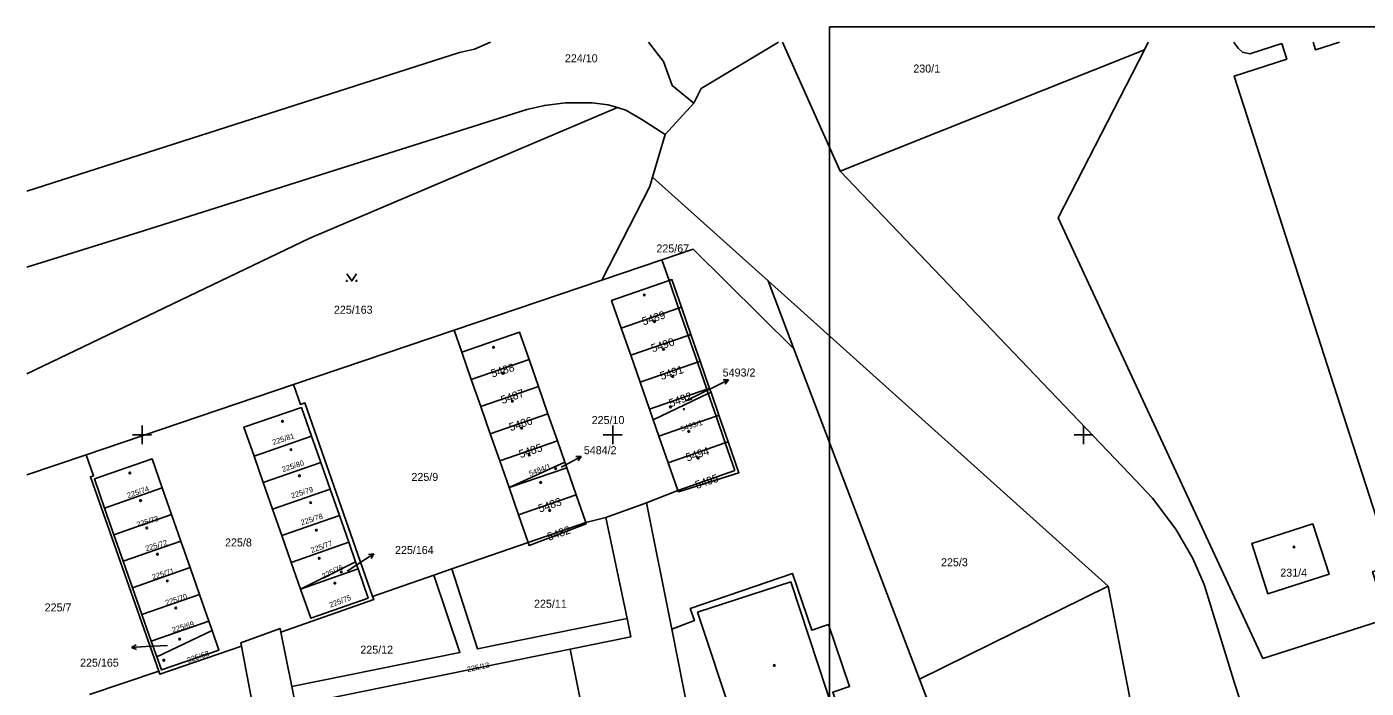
# Model space of a CAD drawing. Extents: x -599970 to -599524, y -1154772 to -1154457.
# Drawn here: x -599962.2 to -599820, y -1154526.9 to -1154456.7 of the extents above; entities that cross this region are included whole.
import ezdxf

# ---------------------------------------------------------------- set-up
doc = ezdxf.new("R2010")
doc.units = 0
for name, color, linetype in [('Z-KATASTRALNI MAPA', 7, 'Continuous'), ('Z-KRIZKY CTVERCOVE SITE', 7, 'Continuous'), ('Z-RAM ROZPISKA', 7, 'Continuous')]:
    doc.layers.add(name, color=color, linetype=linetype)

msp = doc.modelspace()

# ---------------------------------------------------------------- linework, layer by layer
at = {"layer": 'Z-KATASTRALNI MAPA'}
for p, q in [((-599875.84, -1154471.97), (-599881.95, -1154458.29)), ((-599875.84, -1154471.97), (-599843.53, -1154459.09)), ((-599891.38, -1154464.75), (-599894.44, -1154468.08)), ((-599895.76, -1154472.61), (-599894.44, -1154468.08)), ((-599895.76, -1154472.61), (-599883.5, -1154483.62)), ((-599894.78, -1154481.41), (-599901.15, -1154483.56)), ((-599894.02, -1154483.6), (-599894.78, -1154481.41)), ((-599916.86, -1154488.87), (-599901.15, -1154483.56)), ((-599894.02, -1154483.6), (-599893, -1154486.54)), ((-599883.5, -1154483.62), (-599880.75, -1154490.86)), ((-599883.5, -1154483.62), (-599847.36, -1154516.07)), ((-599893, -1154486.54), (-599892, -1154489.43)), ((-599892.7, -1154486.44), (-599891.7, -1154489.33)), ((-599933.91, -1154494.65), (-599916.86, -1154488.87)), ((-599916.04, -1154491.21), (-599916.86, -1154488.87)), ((-599898.09, -1154491.54), (-599899.1, -1154488.65)), ((-599892, -1154489.43), (-599891.01, -1154492.27)), ((-599891.7, -1154489.33), (-599890.71, -1154492.17)), ((-599915.03, -1154494.1), (-599916.04, -1154491.21)), ((-599897.1, -1154494.39), (-599898.09, -1154491.54)), ((-599880.75, -1154490.86), (-599867.42, -1154525.94)), ((-599908.89, -1154491.98), (-599915.03, -1154494.1)), ((-599908.89, -1154491.98), (-599907.88, -1154494.87)), ((-599891.01, -1154492.27), (-599890.01, -1154495.16)), ((-599890.71, -1154492.17), (-599889.71, -1154495.06)), ((-599955.94, -1154502.11), (-599933.91, -1154494.65)), ((-599914.02, -1154496.98), (-599915.03, -1154494.1)), ((-599896.09, -1154497.28), (-599897.1, -1154494.39)), ((-599889.06, -1154494.82), (-599887.71, -1154494.16)), ((-599887.71, -1154494.16), (-599888.27, -1154494.16)), ((-599887.71, -1154494.16), (-599888.05, -1154494.61)), ((-599907.88, -1154494.87), (-599914.02, -1154496.98)), ((-599907.88, -1154494.87), (-599906.88, -1154497.76)), ((-599892.22, -1154496.37), (-599889.06, -1154494.82)), ((-599890.01, -1154495.16), (-599889.85, -1154495.62)), ((-599889.85, -1154495.62), (-599889.02, -1154498.01)), ((-599889.71, -1154495.06), (-599889.56, -1154495.49)), ((-599889.56, -1154495.49), (-599888.72, -1154497.91)), ((-599913.01, -1154499.87), (-599914.02, -1154496.98)), ((-599895.7, -1154498.41), (-599896.09, -1154497.28)), ((-599906.88, -1154497.76), (-599913.01, -1154499.87)), ((-599906.88, -1154497.76), (-599905.87, -1154500.64)), ((-599895.1, -1154500.13), (-599895.7, -1154498.41)), ((-599889.02, -1154498.01), (-599888.04, -1154500.85)), ((-599888.72, -1154497.91), (-599887.74, -1154500.74)), ((-599931.98, -1154500.12), (-599938.1, -1154502.26)), ((-599931.98, -1154500.12), (-599931, -1154502.93)), ((-599912.01, -1154502.76), (-599913.01, -1154499.87)), ((-599894.11, -1154502.97), (-599895.1, -1154500.13)), ((-599912.01, -1154502.76), (-599905.87, -1154500.64)), ((-599905.87, -1154500.64), (-599905.1, -1154502.88)), ((-599887.02, -1154503.79), (-599888.04, -1154500.85)), ((-599955.94, -1154502.11), (-599962.24, -1154504.25)), ((-599937.12, -1154505.07), (-599938.1, -1154502.26)), ((-599931, -1154502.93), (-599937.12, -1154505.07)), ((-599931, -1154502.93), (-599930.02, -1154505.75)), ((-599911.01, -1154505.6), (-599912.01, -1154502.76)), ((-599911.01, -1154505.6), (-599905.1, -1154502.88)), ((-599905.49, -1154503.43), (-599904.68, -1154502.99)), ((-599905.1, -1154502.88), (-599904.89, -1154503.49)), ((-599904.68, -1154502.99), (-599903.35, -1154502.29)), ((-599903.35, -1154502.29), (-599903.92, -1154502.3)), ((-599903.35, -1154502.29), (-599903.68, -1154502.74)), ((-599893.09, -1154505.91), (-599894.11, -1154502.97)), ((-599904.89, -1154503.49), (-599911.01, -1154505.6)), ((-599904.89, -1154503.49), (-599903.88, -1154506.37)), ((-599893.09, -1154505.91), (-599887.02, -1154503.79)), ((-599947.86, -1154505.64), (-599953.98, -1154507.78)), ((-599947.86, -1154505.64), (-599946.87, -1154508.47)), ((-599936.13, -1154507.89), (-599937.12, -1154505.07)), ((-599930.02, -1154505.75), (-599936.13, -1154507.89)), ((-599930.02, -1154505.75), (-599929.03, -1154508.57)), ((-599910.01, -1154508.49), (-599911.01, -1154505.6)), ((-599896.4, -1154507.21), (-599893.09, -1154505.91)), ((-599903.88, -1154506.37), (-599910.01, -1154508.49)), ((-599903.88, -1154506.37), (-599902.86, -1154509.31)), ((-599900.72, -1154508.78), (-599896.4, -1154507.21)), ((-599893.73, -1154520.65), (-599896.4, -1154507.21)), ((-599952.99, -1154510.61), (-599953.98, -1154507.78)), ((-599946.87, -1154508.47), (-599952.99, -1154510.61)), ((-599946.87, -1154508.47), (-599945.88, -1154511.28)), ((-599935.14, -1154510.7), (-599936.13, -1154507.89)), ((-599929.03, -1154508.57), (-599935.14, -1154510.7)), ((-599929.03, -1154508.57), (-599928.04, -1154511.41)), ((-599908.98, -1154511.42), (-599910.01, -1154508.49)), ((-599902.86, -1154509.31), (-599900.72, -1154508.78)), ((-599898.48, -1154519.5), (-599900.72, -1154508.78)), ((-599908.98, -1154511.42), (-599902.86, -1154509.31)), ((-599952.01, -1154513.42), (-599952.99, -1154510.61)), ((-599945.88, -1154511.28), (-599952.01, -1154513.42)), ((-599945.88, -1154511.28), (-599944.9, -1154514.1)), ((-599934.15, -1154513.55), (-599935.14, -1154510.7)), ((-599928.04, -1154511.41), (-599934.15, -1154513.55)), ((-599928.04, -1154511.41), (-599927.32, -1154513.47)), ((-599917.1, -1154514.24), (-599908.98, -1154511.42)), ((-599926.64, -1154513.45), (-599925.38, -1154512.63)), ((-599925.38, -1154512.63), (-599925.94, -1154512.7)), ((-599925.38, -1154512.63), (-599925.67, -1154513.12)), ((-599951.02, -1154516.24), (-599952.01, -1154513.42)), ((-599944.9, -1154514.1), (-599951.02, -1154516.24)), ((-599944.9, -1154514.1), (-599943.9, -1154516.95)), ((-599933.16, -1154516.38), (-599934.15, -1154513.55)), ((-599933.16, -1154516.38), (-599927.32, -1154513.47)), ((-599927.05, -1154514.24), (-599933.16, -1154516.38)), ((-599928.21, -1154514.48), (-599926.64, -1154513.45)), ((-599927.32, -1154513.47), (-599927.05, -1154514.24)), ((-599918.99, -1154514.91), (-599917.1, -1154514.24)), ((-599925.51, -1154517.16), (-599918.99, -1154514.91)), ((-599891, -1154518.82), (-599881.1, -1154515.6)), ((-599881.1, -1154515.6), (-599875.33, -1154533.01)), ((-599867.42, -1154525.94), (-599847.36, -1154516.07)), ((-599847.36, -1154516.07), (-599840.68, -1154550.58)), ((-599950.03, -1154519.09), (-599951.02, -1154516.24)), ((-599943.9, -1154516.95), (-599950.03, -1154519.09)), ((-599943.9, -1154516.95), (-599942.91, -1154519.78)), ((-599891, -1154518.82), (-599885.15, -1154536.36)), ((-599949.04, -1154521.92), (-599950.03, -1154519.09)), ((-599949.04, -1154521.92), (-599942.91, -1154519.78)), ((-599942.91, -1154519.78), (-599942.56, -1154520.77)), ((-599942.56, -1154520.77), (-599948.43, -1154523.58)), ((-599935.24, -1154520.95), (-599934.08, -1154526.74)), ((-599890.22, -1154538.37), (-599893.73, -1154520.65)), ((-599951.11, -1154522.57), (-599950.62, -1154522.29)), ((-599949.61, -1154522.49), (-599951.11, -1154522.57)), ((-599951.11, -1154522.57), (-599950.6, -1154522.79)), ((-599947.29, -1154522.38), (-599949.61, -1154522.49)), ((-599948.43, -1154523.58), (-599949.04, -1154521.92)), ((-599939.42, -1154522.44), (-599937.69, -1154531.73)), ((-599933.69, -1154528.7), (-599904.52, -1154522.77)), ((-599955.57, -1154527.59), (-599948.23, -1154525.08)), ((-599934.08, -1154526.74), (-599933.69, -1154528.7))]:
    msp.add_line(p, q, dxfattribs=at)
for points in [[(-599962.24, -1154474.12), (-599916.27, -1154459.39), (-599914.68, -1154459.01), (-599912.98, -1154458.29)], [(-599896.19, -1154458.29), (-599894.62, -1154460.32), (-599893.67, -1154462.88), (-599891.38, -1154464.75)], [(-599882.41, -1154458.29), (-599890.62, -1154463.2), (-599891.38, -1154464.75)], [(-599843.53, -1154459.09), (-599852.7, -1154476.94), (-599830.94, -1154523.74), (-599794.88, -1154512.22)], [(-599843.12, -1154458.29), (-599843.53, -1154459.09)], [(-599834.01, -1154458.29), (-599834, -1154458.35), (-599833.58, -1154458.92), (-599833.1, -1154459.33), (-599832.33, -1154459.52), (-599828.94, -1154458.42)], [(-599828.94, -1154458.42), (-599828.4, -1154460.08), (-599833.99, -1154461.88), (-599817.26, -1154513.88), (-599819.29, -1154514.53), (-599818.39, -1154517.37), (-599802.13, -1154512.18), (-599807.35, -1154495.82), (-599805.22, -1154495.14)], [(-599822.81, -1154458.29), (-599825.34, -1154459.1), (-599825.61, -1154458.29)], [(-599899.51, -1154465.24), (-599900.48, -1154464.94), (-599902.2, -1154464.73), (-599905, -1154464.73), (-599907.25, -1154465.01), (-599909.11, -1154465.44), (-599949.83, -1154478.34), (-599962.24, -1154482.17)], [(-599962.24, -1154493.52), (-599932.19, -1154479.12), (-599899.51, -1154465.24)], [(-599894.44, -1154468.08), (-599896.91, -1154466.5), (-599898.62, -1154465.52), (-599899.51, -1154465.24)], [(-599820, -1154569.28), (-599833.91, -1154526.47), (-599837.18, -1154515.88), (-599838.39, -1154513.13), (-599840.19, -1154510.02), (-599842.65, -1154506.72), (-599845.1, -1154504.12), (-599875.84, -1154471.97)], [(-599901.15, -1154483.56), (-599896.05, -1154473.6), (-599895.76, -1154472.61)], [(-599880.75, -1154490.86), (-599891.46, -1154480.28), (-599894.78, -1154481.41)], [(-599928.23, -1154482.9), (-599927.73, -1154483.65), (-599927.23, -1154482.9)], [(-599899.1, -1154488.65), (-599900.12, -1154485.71), (-599894.02, -1154483.6)], [(-599894.02, -1154483.6), (-599893.72, -1154483.5), (-599892.7, -1154486.44)], [(-599899.1, -1154488.65), (-599893, -1154486.54), (-599892.7, -1154486.44)], [(-599916.04, -1154491.21), (-599909.89, -1154489.09), (-599908.89, -1154491.98)], [(-599898.09, -1154491.54), (-599892, -1154489.43), (-599891.7, -1154489.33)], [(-599897.1, -1154494.39), (-599891.01, -1154492.27), (-599890.71, -1154492.17)], [(-599925.51, -1154517.16), (-599932.7, -1154496.6), (-599933.17, -1154496.77), (-599933.91, -1154494.65)], [(-599896.09, -1154497.28), (-599890.01, -1154495.16), (-599889.71, -1154495.06)], [(-599889.56, -1154495.49), (-599889.85, -1154495.62), (-599895.7, -1154498.41)], [(-599938.1, -1154502.26), (-599939.17, -1154499.19), (-599933.06, -1154497.09), (-599931.98, -1154500.12)], [(-599888.72, -1154497.91), (-599889.02, -1154498.01), (-599895.1, -1154500.13)], [(-599894.11, -1154502.97), (-599888.04, -1154500.85), (-599887.74, -1154500.74)], [(-599887.74, -1154500.74), (-599886.6, -1154504.02), (-599893.03, -1154506.04), (-599893.09, -1154505.91)], [(-599948.23, -1154525.08), (-599955.49, -1154504.45), (-599955.15, -1154504.35), (-599955.94, -1154502.11)], [(-599953.98, -1154507.78), (-599955.04, -1154504.67), (-599948.93, -1154502.56), (-599947.86, -1154505.64)], [(-599902.86, -1154509.31), (-599902.83, -1154509.44), (-599908.87, -1154511.75), (-599908.98, -1154511.42)], [(-599825.64, -1154509.44), (-599823.91, -1154514.8), (-599830.4, -1154516.89), (-599832.13, -1154511.52), (-599825.64, -1154509.44)], [(-599927.05, -1154514.24), (-599925.98, -1154517.33), (-599932.08, -1154519.47), (-599933.16, -1154516.38)], [(-599917.1, -1154514.24), (-599914.38, -1154522.73), (-599898.48, -1154519.5)], [(-599934.08, -1154526.74), (-599916.24, -1154523.11), (-599918.99, -1154514.91)], [(-599893.73, -1154520.65), (-599891.32, -1154519.73), (-599891.77, -1154518.45), (-599880.91, -1154514.72), (-599878.86, -1154520.74), (-599877.08, -1154520.15), (-599874.85, -1154526.74), (-599876.63, -1154527.34), (-599874.57, -1154533.38), (-599876.97, -1154534.24)], [(-599935.24, -1154520.95), (-599925.39, -1154517.49), (-599925.51, -1154517.16)], [(-599904.52, -1154522.77), (-599898.08, -1154521.46), (-599898.48, -1154519.5)], [(-599942.56, -1154520.77), (-599941.83, -1154522.88), (-599947.93, -1154524.97), (-599948.43, -1154523.58)], [(-599939.42, -1154522.44), (-599939.49, -1154522.07), (-599935.32, -1154520.57), (-599935.24, -1154520.95)], [(-599948.23, -1154525.08), (-599948.12, -1154525.4), (-599939.42, -1154522.44)], [(-599888.41, -1154570.07), (-599889.85, -1154562.6), (-599896.31, -1154563.92), (-599904.52, -1154522.77)], [(-599856.06, -1154556.68), (-599857.37, -1154552.41), (-599867.42, -1154525.94)]]:
    msp.add_lwpolyline(points, dxfattribs=at)
for centre, radius in [((-599928.23, -1154483.65), 0.05), ((-599927.23, -1154483.65), 0.05), ((-599896.64, -1154485.14), 0.0875), ((-599895.56, -1154487.97), 0.0875), ((-599912.66, -1154490.7), 0.0875), ((-599894.6, -1154490.91), 0.0875), ((-599911.63, -1154493.45), 0.0875), ((-599893.63, -1154493.79), 0.0875), ((-599910.66, -1154496.41), 0.0875), ((-599893.87, -1154497.02), 0.0875), ((-599892.44, -1154497.27), 0.0586), ((-599935.08, -1154498.56), 0.0875), ((-599909.67, -1154499.28), 0.0875), ((-599891.92, -1154499.64), 0.0875), ((-599934.18, -1154501.56), 0.0875), ((-599908.87, -1154502.13), 0.0875), ((-599890.92, -1154502.45), 0.0875), ((-599951.29, -1154504.04), 0.0875), ((-599933.28, -1154504.34), 0.0875), ((-599906.06, -1154503.59), 0.0875), ((-599907.66, -1154505.05), 0.0875), ((-599950.16, -1154506.97), 0.0875), ((-599932.08, -1154507.19), 0.0875), ((-599906.7, -1154508.03), 0.0875), ((-599949.49, -1154509.89), 0.0875), ((-599931.48, -1154510.12), 0.0875), ((-599827.64, -1154511.9), 0.0875), ((-599948.36, -1154512.67), 0.0875), ((-599931.18, -1154513.12), 0.0875), ((-599928.83, -1154514.56), 0.0875), ((-599947.31, -1154515.52), 0.0875), ((-599929.52, -1154515.75), 0.0875), ((-599946.41, -1154518.38), 0.0875), ((-599946.01, -1154521.69), 0.0875), ((-599947.69, -1154523.93), 0.0875), ((-599882.83, -1154524.49), 0.0875)]:
    msp.add_circle(centre, radius, dxfattribs=at)
at = {"layer": 'Z-KRIZKY CTVERCOVE SITE'}
for p, q in [((-599950, -1154501), (-599950, -1154499)), ((-599900, -1154501), (-599900, -1154499)), ((-599850, -1154501), (-599850, -1154499)), ((-599949, -1154500), (-599951, -1154500)), ((-599899, -1154500), (-599901, -1154500)), ((-599849, -1154500), (-599851, -1154500))]:
    msp.add_line(p, q, dxfattribs=at)
at = {"layer": 'Z-RAM ROZPISKA'}
msp.add_lwpolyline([(-599876.98, -1154456.65), (-599579.98, -1154456.65), (-599579.98, -1154771.65), (-599876.98, -1154771.65)], close=True, dxfattribs=at)

# ---------------------------------------------------------------- texts
at = {"layer": 'Z-KATASTRALNI MAPA'}
for s, p in [('224/10', (-599905.08, -1154460.42)), ('230/1', (-599868.07, -1154461.51)), ('225/67', (-599895.36, -1154480.62)), ('225/163', (-599929.62, -1154487.13)), ('5493/2', (-599888.32, -1154493.8)), ('225/10', (-599902.24, -1154498.85)), ('5484/2', (-599903.07, -1154502.05)), ('225/9', (-599921.38, -1154504.89)), ('225/8', (-599941.18, -1154511.85)), ('225/164', (-599923.13, -1154512.65)), ('225/3', (-599865.13, -1154513.95)), ('231/4', (-599829.09, -1154515.06)), ('225/11', (-599908.36, -1154518.36)), ('225/7', (-599960.34, -1154518.75)), ('225/12', (-599926.81, -1154523.24)), ('225/165', (-599956.58, -1154524.62))]:
    msp.add_text(s, height=0.85, dxfattribs=at).set_placement(p)
for s, height, rotation, p in [('5489', 0.85, 18, (-599896.73, -1154488.38)), ('5490', 0.85, 18, (-599895.76, -1154491.24)), ('5488', 0.85, 17, (-599912.78, -1154493.92)), ('5491', 0.85, 18, (-599894.82, -1154494.18)), ('5487', 0.85, 19, (-599911.72, -1154496.73)), ('5492', 0.85, 20, (-599893.85, -1154497.08)), ('5486', 0.85, 18, (-599910.85, -1154499.61)), ('5493/1', 0.57, 18, (-599892.69, -1154499.66)), ('225/81', 0.57, 18, (-599936.05, -1154501.08)), ('5485', 0.85, 18, (-599909.8, -1154502.48)), ('5494', 0.85, 18, (-599892.08, -1154502.84)), ('225/80', 0.57, 18, (-599935.02, -1154503.95)), ('5484/1', 0.57, 21, (-599908.77, -1154504.4)), ('5495', 0.85, 19, (-599891.07, -1154505.76)), ('225/74', 0.57, 19, (-599951.47, -1154506.73)), ('225/79', 0.57, 18, (-599934.06, -1154506.76)), ('5483', 0.85, 19, (-599907.74, -1154508.26)), ('225/73', 0.57, 17, (-599950.49, -1154509.82)), ('225/78', 0.57, 18, (-599933.03, -1154509.61)), ('5482', 0.85, 19, (-599906.78, -1154511.26)), ('225/72', 0.57, 17, (-599949.55, -1154512.37)), ('225/77', 0.57, 20, (-599931.96, -1154512.55)), ('225/71', 0.57, 17, (-599948.83, -1154515.38)), ('225/76', 0.57, 26, (-599930.73, -1154515.31)), ('225/70', 0.57, 18, (-599947.42, -1154518.13)), ('225/75', 0.57, 21, (-599929.98, -1154518.36)), ('225/69', 0.57, 17, (-599946.71, -1154521.01)), ('225/68', 0.57, 19, (-599945.09, -1154524.22)), ('225/13', 0.57, 12, (-599915.41, -1154525.2))]:
    msp.add_text(s, height=height, rotation=rotation, dxfattribs=at).set_placement(p)

doc.saveas('drawing.dxf')
